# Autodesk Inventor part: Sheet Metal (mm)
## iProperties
Shininess: 64.0
Length Units: 11269
Angle Units: 11279
Time Units: 11290
Mass Units: 11283
Length Display Precision: 3
Angle Display Precision: 2
Compacted: True
Part Number: Sheet Metal (mm)
Document SubType Name: Sheet Metal
Created: 2002-07
Density: 1 g/cm^3
Sheet Metal Rule: Default
Density: 0.0
Volumn: 0.0
Area: 0.0
PropertySet Name: Model Information
Control State: 0
Master: False
Checked Out: False
